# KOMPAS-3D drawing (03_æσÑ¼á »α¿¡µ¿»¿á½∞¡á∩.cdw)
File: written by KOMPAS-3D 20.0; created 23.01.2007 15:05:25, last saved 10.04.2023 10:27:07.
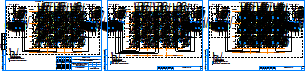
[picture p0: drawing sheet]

Sheets 1-3: A3, landscape

Document properties: Автор: Лескин; Организация: ЗАО ИТФ "СИСТЕМЫ И ТЕХНОЛОГИИ"; Разработал: Антошин; Проверил: Тарасов; Утвердил: Шмончев; Н. контр.: Силаков; Форматы листов документа: 3xA3; Полное имя файла: \\s-tech\depts\Отдел_ПКО\Проекты\Типовые проекты МКД 2023\!Типовой проект\1_Типовой проект МКД_RS-485\03_Схема принципиальная.cdw

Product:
- Part/product: (unnamed)
  - Component: \\Helios\отдел_пко\Общая папка Компас\_Addons\Signatures\Signatures.lfr|Шмончев  | Полное имя файла: C:\Users\MAntoshin\AppData\Local\Temp\hsklda.frw; source file: C:\Program Files\ASCON\KOMPAS-3D V13\Libs\_Addons\Signatures\Signatures.lfr
  - Component: \\Helios\отдел_пко\Общая папка Компас\_Addons\Signatures\Signatures.lfr|Силаков  | Полное имя файла: C:\Users\MAntoshin\AppData\Local\Temp\eiczbt.frw; source file: C:\Program Files\ASCON\KOMPAS-3D V13\Libs\_Addons\Signatures\Signatures.lfr
  - Component: \\Helios\отдел_пко\Общая папка Компас\_Addons\Signatures\Signatures.lfr|Тарасов  | Полное имя файла: C:\Users\MAntoshin\AppData\Local\Temp\qlkzkl.frw; source file: C:\Program Files\ASCON\KOMPAS-3D V13\Libs\_Addons\Signatures\Signatures.lfr

Title block, sheet 1: designation: ВЛСТ 1277.01.000 СЭ; sheet number: 1; Количество листов документа: 3; organisation: АО ГК / "Системы и Технологии"; Форматы листов документа: A3; stored path: C:\Program Files\ASCON\KOMPAS-3D V8 Plus\Templates\Чертеж строительный зданий и сооружений.cdt; cell 302: Система учета электроэнергии (с организацией удаленного / сбора данных) потребителей; cell 303: Типовой проект ИСУЭ многоквартирного / дома с использованием проводного / канала связи RS-485; cell 304: Схема принципиальная; cell 320: Р
Title block, sheet 2: sheet number: 2; stored path: Z:\Проекты\ЭнергоКурган\СЭ_Схема однолинейная.cdw
Title block, sheet 3: sheet number: 3; Форматы листов документа: A4; designation, second copy: ВЛСТ 1277.01.000 СЭ-

Referenced files in \\Helios\отдел_пко\Общая папка Компас\_Addons\Signatures\: Signatures.lfr|Тарасов, Signatures.lfr, Signatures.lfr|Силаков, Signatures.lfr|Шмончев
Referenced files in C:\Program Files\ASCON\KOMPAS-3D V13\Libs\_Addons\Signatures\: Signatures.lfr
Referenced files: qlkzkl.frw, eiczbt.frw, hsklda.frw
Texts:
  Тарасов
  Силаков
  Шмончев
  Normal
  Body Text,Письмо в Интернет,body text
  TXT
  Centerline
  Outline
  АВР
  Ввод 1
  Ввод 2
  Лифтовое
  оборудование
  Этажные
  щиты
  Общедомойвые
  нужды
  МКД
  Кв.1
  Кв.2
  Тех. этаж
  Подъезд 1
  Подвал
  Подъезд 2
  Ввод 3
  Ввод 4
  Общедомойвой
  учет
  Подъезд N
  Кв.3
  Кв.4
  Кв.5
  Кв.6
  Вариант 1. Многоквартирный дом с этажностью - до 5
  Вариант 2. Многоквартирный дом с этажностью - 9
  Вариант 3/4. Многоквартирный дом с этажностью - 14-18
  - счетчик электрической энергии;
  - измерительные трансформаторы тока.
  POLYLINE_STYLE_0.09_RGB_0_0_0
  POLYLINE_STYLE_0.18_RGB_0_0_0
  POLYLINE_STYLE_0.09_RGB_0_0_255
  Черная основная
  Красная штриховая
  сплошная своя 0,54 мм на бумаге
  Красная основная
  CONTINUOUS0
  POLYLINE_STYLE_0.18_RGB_255_0_0
  CONTINUOUS_RGB_0_0_0_THICK_0.25
  Стили документа
  Разраб.
  Н.контр.
  Утв.
  Антошин
  03 Рабочие чертежи основного комплекта. ГОСТ 21.101-97 Ф3
  05 Чертежи строительных изделий. Посл. листы. ГОСТ Р 21.1101-2009 Ф6
Dimensions and other numbers on the sheet: 1,8; 2,5; 1 эт, ВРУ №1; 1 эт; 2-17 эт; 18 эт; 1 эт, ВРУ №2; 2-4 эт; 5 эт; 1; 04.23; 3; 2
